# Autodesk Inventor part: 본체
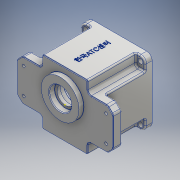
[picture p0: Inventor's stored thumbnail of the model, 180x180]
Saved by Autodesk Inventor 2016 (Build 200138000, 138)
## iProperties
Created: 2017-01
Part Number: 본체
Material: 알루미늄 6061
Document SubType Name: Modeling
Designer: Owner
Mass: 876.679 g
Surface Area: 765.057 cm^2
Volume: 324.696 cm^3
Density: 2.7 g/cm^3
Appearance: 알루미늄 - 평지
Author: Owner
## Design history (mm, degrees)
sketch "스케치1"
  geometry: L1 (47, -47)-(-47, -47); L2 (-47, -47)-(-47, 47); L3 (-47, 47)-(47, 47); L4 (47, 47)-(47, -47); L5 (47, -47)-(-47, 47); L6 (-47, -47)-(47, 47); 1 further point
  constraints: 12 end point, 2 midpoint, 2 parallel, 1 horizontal, 1 perpendicular
  dimensions: "d0" = 94 distance of L2.end L3.end; "d1" = 94 distance of L1.end L2.end
extrude "돌출1" new body sketch "스케치1" distance "d2" = 80; taper "d3" = 0 deg
sketch "스케치2"
  geometry: L1 (47, -47)-(47, 47) reference; L2 (47, 47)-(33, 47); L3 (33, 47)-(33, 30); L4 (33, 30)-(47, 30); L5 (47, 30)-(47, 47); 1 further point
  constraints: 8 end point, 2 parallel, 1 horizontal, 1 perpendicular
  dimensions: "d4" = 14 distance of L1.end L2.end; "d5" = 17 distance between parallel lines of L4 L2
extrude "돌출2" cut sketch "스케치2" distance "d6" = 70; taper "d7" = 0 deg
sketch "스케치3"
  geometry: L1 (47, 30)-(70, 30); L2 (70, 30)-(70, -30); L3 (70, -30)-(47, -30); L4 (47, -30)-(47, 30); 3 further points
  constraints: 8 end point, 2 coincident, 2 parallel, 1 horizontal, 1 perpendicular
  dimensions: "d8" = 70 distance from line of L2 point (0, 0)
extrude "돌출3" join sketch "스케치3" distance "d9" = 13; taper "d10" = 0 deg
chamfer "모따기1" distance "d11" = 8; stored, may be unused: second distance "d12" = 2, angle "d13" = 45 deg
sketch "스케치4"
  geometry: 2 further points
  constraints: 1 coincident
hole "구멍1" sketch "스케치4" at (0, 0) diameter "d14" = 80; stored, may be unused: countersink angle "d18" = 90 deg, drill point angle "d20" = 0 deg; dims "d15" = 6, "d16" = 86, "d17" = 9, "d19" = 71
sketch "스케치6"
  geometry: A1 r 4 centre (-36, 0) between (-35.852, -3.997) and (-35.852, 3.997); A2 r 40 centre (0, 0) between (-39.148, -8.214) and (-39.148, 8.214) reference; A3 r 3.5 centre (-35.722, -7.495) between (-35.852, -3.997) and (-39.148, -8.214); A4 r 3.5 centre (-35.722, 7.495) between (-39.148, 8.214) and (-35.852, 3.997); 1 further point
  constraints: 8 point on circle, 4 tangent, 3 centre point, 1 horizontal alignment
  dimensions: "d21" = 8 diameter of A1; "d22" = 36 distance of A1.centre point (0, 0); "d23" = 7 diameter of A3; "d24" = 7 diameter of A4
extrude "돌출4" join sketch "스케치6" stored distance "d25" = 13; taper "d26" = 0 deg
hole "구멍2" diameter "d29" = 3.242; stored, may be unused: countersink angle "d33" = 90 deg, drill point angle "d35" = 118 deg; dims "d30" = 7, "d31" = 86, "d32" = 9, "d34" = 9, "d52" = 10, "d53" = 10
sketch "스케치7"
  geometry: A1 r 21 centre (36, -11) between (27.022, 7.984) and (44.978, 7.984); A2 r 15 centre (36, 20) between (44.978, 7.984) and (27.022, 7.984); 1 further point
  constraints: 4 point on circle, 2 centre point, 2 vertical alignment
  dimensions: "d36" = 11 distance of point (36, 0) A1.centre; "d37" = 20 distance of A2.centre point (36, 0); "d38" = 42 diameter of A1; "d39" = 30 diameter of A2
extrude "돌출5" join sketch "스케치7" distance "d40" = 7; taper "d41" = 0 deg
fillet "모깎기1" dims "d42" = 3
hole "구멍3" diameter "d45" = 19; stored, may be unused: countersink angle "d49" = 90 deg, drill point angle "d51" = 0 deg; dims "d43" = 10, "d44" = 10, "d46" = 7, "d47" = 22, "d48" = 7, "d50" = 8
hole "구멍4" diameter "d56" = 25; stored, may be unused: countersink angle "d60" = 90 deg, drill point angle "d62" = 0 deg; dims "d54" = 10, "d55" = 10, "d57" = 7, "d58" = 35, "d59" = 10, "d61" = 8
sketch "스케치8"
  geometry: C1 r 12.5 at (0, 11) reference; C2 r 27.5 at (0, 11); 1 further point
  constraints: 1 centre point, 1 coincident
  dimensions: "d63" = 55 diameter of C2
extrude "돌출6" join sketch "스케치8" distance "d64" = 7; taper "d65" = 0 deg
sketch "스케치9"
  geometry: C1 r 12.5 at (0, 0) reference; C2 r 16 at (0, 0); 1 further point
  constraints: 1 centre point, 1 coincident
  dimensions: "d66" = 32 diameter of C2
extrude "돌출7" cut sketch "스케치9" distance "d67" = 8; taper "d68" = 0 deg
chamfer "모따기2" distance "d69" = 1; stored, may be unused: second distance "d70" = 2, angle "d71" = 45 deg
fillet "모깎기2" dims "d72" = 0.3
fillet "모깎기3" dims "d73" = 2
fillet "모깎기4" dims "d74" = 2
sketch "스케치12"
  geometry: 2 further points
  dimensions: "d75" = 19 vertical distance of point (47, 30) point (-13, 11); "d76" = 60 horizontal distance of point (-13, 11) point (47, 30)
hole "구멍5" sketch "스케치12" at (-13, 11) diameter "d77" = 4; stored, may be unused: countersink angle "d81" = 90 deg, drill point angle "d83" = 0 deg; dims "d78" = 7, "d79" = 10, "d80" = 4, "d82" = 8
sketch "스케치13"
  geometry: 1 further point
fillet "모깎기5" dims "d84" = 5
fillet "모깎기6" dims "d85" = 2
fillet "모깎기7" dims "d86" = 5
fillet "모깎기8" dims "d87" = 8
fillet "모깎기9" dims "d88" = 2
sketch "스케치14"
  geometry: L1 (-33, 45)-(-33, 35) reference; L2 (-38, 30)-(-59.929, 30) reference; L3 (-68.536, 23.464)-(-63.464, 28.536) reference; L4 (-70, 19.929)-(-70, -19.929) reference; L5 (-63.464, -28.536)-(-68.536, -23.464) reference; L6 (-59.929, -30)-(-38, -30) reference; L7 (-33, -35)-(-33, -45) reference; L8 (-31, -47)-(31, -47) reference; L9 (33, -45)-(33, -35) reference; L10 (59.929, -30)-(38, -30) reference; L11 (68.536, -23.464)-(63.464, -28.536) reference; L12 (70, 19.929)-(70, -19.929) reference; L13 (63.464, 28.536)-(68.536, 23.464) reference; L14 (59.929, 30)-(38, 30) reference; L15 (33, 35)-(33, 45) reference; L16 (31, 47)-(-31, 47) reference; L17 (-32, 45)-(-32, 35); L18 (-38, 29)-(-59.929, 29); L19 (-62.757, 27.828)-(-67.828, 22.757); L20 (-69, 19.929)-(-69, -19.929); L21 (-67.828, -22.757)-(-62.757, -27.828); L22 (-59.929, -29)-(-38, -29); L23 (-32, -35)-(-32, -45); L24 (-31, -46)-(31, -46); L25 (32, -45)-(32, -35); L26 (38, -29)-(59.929, -29); L27 (62.757, -27.828)-(67.828, -22.757); L28 (69, -19.929)-(69, 19.929); L29 (67.828, 22.757)-(62.757, 27.828); L30 (59.929, 29)-(38, 29); L31 (32, 35)-(32, 45); L32 (31, 46)-(-31, 46); C1 r 2 at (60, -19) reference; C2 r 2 at (-60, -19) reference; C3 r 2 at (60, 19) reference; C4 r 2 at (-60, 19) reference; C5 r 27.5 at (0, 11) reference; A1 r 2 centre (-31, 45) between (-31, 47) and (-33, 45) reference; A2 r 5 centre (-38, 35) between (-38, 30) and (-33, 35) reference; A3 r 5 centre (-59.929, 25) between (-59.929, 30) and (-63.464, 28.536) reference; A4 r 5 centre (-65, 19.929) between (-68.536, 23.464) and (-70, 19.929) reference; A5 r 5 centre (-65, -19.929) between (-70, -19.929) and (-68.536, -23.464) reference; A6 r 5 centre (-59.929, -25) between (-63.464, -28.536) and (-59.929, -30) reference; A7 r 5 centre (-38, -35) between (-33, -35) and (-38, -30) reference; A8 r 2 centre (-31, -45) between (-33, -45) and (-31, -47) reference; A9 r 2 centre (31, -45) between (31, -47) and (33, -45) reference; A10 r 5 centre (38, -35) between (38, -30) and (33, -35) reference; A11 r 5 centre (59.929, -25) between (59.929, -30) and (63.464, -28.536) reference; A12 r 5 centre (65, -19.929) between (68.536, -23.464) and (70, -19.929) reference; A13 r 5 centre (65, 19.929) between (70, 19.929) and (68.536, 23.464) reference; A14 r 5 centre (59.929, 25) between (63.464, 28.536) and (59.929, 30) reference; A15 r 5 centre (38, 35) between (33, 35) and (38, 30) reference; A16 r 2 centre (31, 45) between (33, 45) and (31, 47) reference; A17 r 1 centre (-31, 45) between (-31, 46) and (-32, 45); A18 r 6 centre (-38, 35) between (-38, 29) and (-32, 35); A19 r 4 centre (-59.929, 25) between (-59.929, 29) and (-62.757, 27.828); A20 r 4 centre (-65, 19.929) between (-67.828, 22.757) and (-69, 19.929); A21 r 4 centre (-65, -19.929) between (-69, -19.929) and (-67.828, -22.757); A22 r 4 centre (-59.929, -25) between (-62.757, -27.828) and (-59.929, -29); A23 r 6 centre (-38, -35) between (-32, -35) and (-38, -29); A24 r 1 centre (-31, -45) between (-32, -45) and (-31, -46); A25 r 1 centre (31, -45) between (31, -46) and (32, -45); A26 r 6 centre (38, -35) between (38, -29) and (32, -35); A27 r 4 centre (59.929, -25) between (59.929, -29) and (62.757, -27.828); A28 r 4 centre (65, -19.929) between (67.828, -22.757) and (69, -19.929); A29 r 4 centre (65, 19.929) between (69, 19.929) and (67.828, 22.757); A30 r 4 centre (59.929, 25) between (62.757, 27.828) and (59.929, 29); A31 r 6 centre (38, 35) between (32, 35) and (38, 29); A32 r 1 centre (31, 45) between (32, 45) and (31, 46); 1 further point
  constraints: 32 end point, 32 point on circle, 16 centre point, 31 other
  dimensions: "d89" = 1 distance between parallel lines of L16 L32
extrude "돌출8" cut sketch "스케치14" distance "d90" = 1; taper "d91" = 0 deg
fillet "모깎기10" dims "d92" = 0.3
sketch "스케치15"
  geometry: L1 (78, 0)-(0, 0) reference; 3 further points
  constraints: 1 midpoint, 1 vertical alignment, 1 other
  dimensions: "d93" = 40 distance of point (39, -40) point (39, 0)
feature "엠보싱1" sketch "스케치15" dims "d94" = 0.5, "d95" = 0
sketch "스케치16"
  geometry: C1 r 3.5 at (40, 40); 1 further point
  constraints: 1 centre point
  dimensions: "d96" = 40 horizontal distance of point (0, 0) C1.centre; "d97" = 40 horizontal distance of C1.centre point (0, 0); "d98" = 7 diameter of C1
extrude "돌출9" cut sketch "스케치16" stored distance "d99" = 1; taper "d100" = 0 deg
fillet "모깎기11" dims "d101" = 0.3
node "솔리드1"
mirror "대칭1"
mirror "대칭2"
mirror "대칭3"
mirror "대칭4"
mirror "대칭5"
mirror "대칭6"
mirror "대칭7"
mirror "대칭8"
node "투영된 루프1"
